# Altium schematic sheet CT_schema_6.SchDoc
size 277 x 170 mm
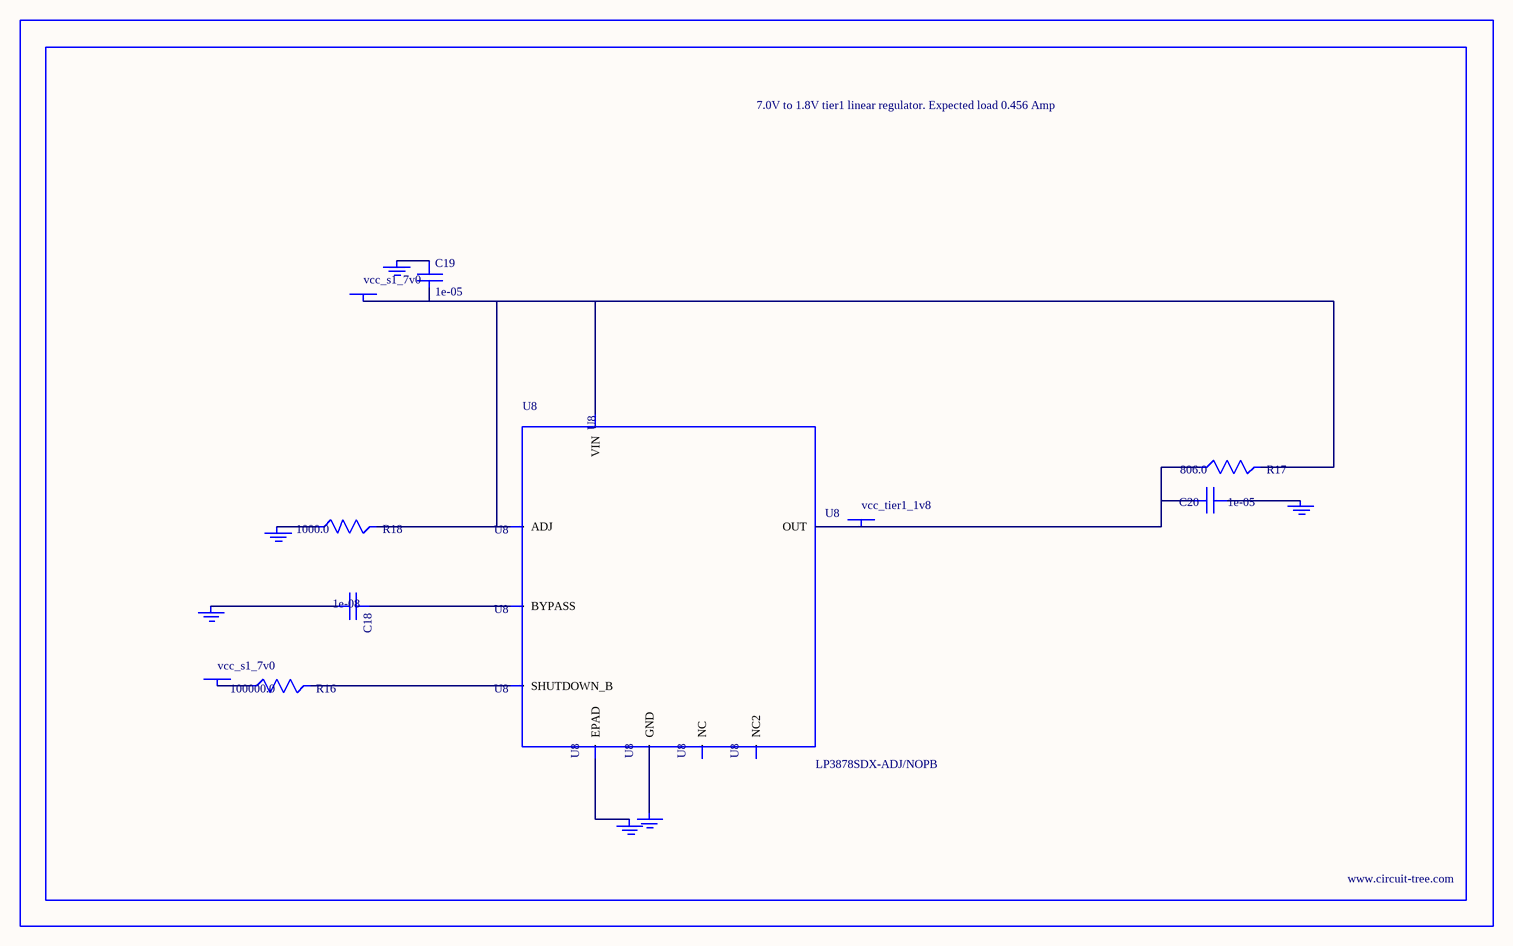
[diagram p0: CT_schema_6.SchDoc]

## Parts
BORDER5  (no value)
C18  1e-08  [C0402]
C19  1e-05  [C1206]
C20  1e-05  [C0805]
GND_INSTANCE_5_0  (no value)
GND_INSTANCE_5_1  (no value)
GND_INSTANCE_5_2  (no value)
GND_INSTANCE_5_3  (no value)
GND_INSTANCE_5_4  (no value)
GND_INSTANCE_5_5  (no value)
POWER_INSTANCE_5_0  vcc_s1_7v0
POWER_INSTANCE_5_1  vcc_s1_7v0
POWER_INSTANCE_5_2  vcc_tier1_1v8
R16  100000.0  [R0603]
R17  806.0  [R0603]
R18  1000.0  [R0603]
U8  LP3878SDX-ADJ/NOPB  [WSON-8]

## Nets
NetC18_1: C18.1 U8.1(BYPASS)
NetC18_2: C18.2 GND_INSTANCE_5_0.0(GND)
NetC19_1: C19.1 GND_INSTANCE_5_1.0(GND)
NetC19_2: C19.2 POWER_INSTANCE_5_0.0(PWR) R17.2 R18.2 U8.4(VIN) U8.6(ADJ)
NetC20_1: C20.1 GND_INSTANCE_5_2.0(GND)
NetC20_2: C20.2 POWER_INSTANCE_5_2.0(PWR) R17.1 U8.5(OUT)
NetGND_INSTANCE_5_3_0: GND_INSTANCE_5_3.0(GND) R18.1
NetGND_INSTANCE_5_4_0: GND_INSTANCE_5_4.0(GND) U8.PAD(EPAD)
NetGND_INSTANCE_5_5_0: GND_INSTANCE_5_5.0(GND) U8.3(GND)
NetPOWER_INSTANCE_5_1_0: POWER_INSTANCE_5_1.0(PWR) R16.1
NetR16_2: R16.2 U8.8(SHUTDOWN_B)

Not connected (* = marked no-connect by the designer): U8 2(NC) 7(NC2)

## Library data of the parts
BORDER5 = BORDER_PAGE5
C18 = C0402C103K3RAC
C19 = C1206C106K3RACTU
C20 = GRM219R60J106ME19D
GND_INSTANCE_5_0-GND_INSTANCE_5_5 = GND
POWER_INSTANCE_5_0-POWER_INSTANCE_5_2 = PWR
R16 = RC0603JR-07100KL
R17 = ERJ-3EKF8060V
R18 = RC0603JR-071KL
